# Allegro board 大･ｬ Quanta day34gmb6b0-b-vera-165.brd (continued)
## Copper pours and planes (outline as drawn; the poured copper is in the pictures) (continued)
GND on IN1 (solid shape): 76.93,83.49 76.93,80.16 76.73,79.96 75.39,79.96 74.93,79.5 74.37,79.5 74.32,79.45 74.28,79.43 74.25,79.45 73.2,80.49 73.2,82.8 74.15,83.75 74.63,83.75 75.15,84.26 76.16,84.26
GND on IN1 (solid shape): outline of 144 points within 94.31,44.17 101.62,55.45
GND on IN1 (solid shape): outline of 1586 points within 6.96,5.96 205.29,192.29
GND on IN1 (solid shape): outline of 4035 points within 0.51,0.51 149.88,159.9
GND on IN2 (solid shape): 24.23,118.34 24.23,115.72 24.18,115.67 21.61,115.67 21.54,115.75 21.54,118.31 21.59,118.36 24.2,118.36
GND on IN2 (solid shape): 154,117.83 154,114.73 153.82,114.55 150.95,114.55 150.7,114.81 150.7,117.98 150.95,118.24 153.59,118.24
GND on IN2 (solid shape): 175.92,74.09 175.92,72.7 175.79,72.57 175.16,72.57 175.03,72.7 175.03,74.09 175.16,74.22 175.79,74.22
GND on IN2 (solid shape): 187.09,16.05 187.09,10.59 186.94,10.44 182.85,10.44 182.5,10.8 182.5,15.75 183.18,16.43 186.71,16.43
GND on IN2 (solid shape): 24.13,75.01 24.13,73.43 24.08,73.38 22.45,73.38 22.4,73.43 22.4,75.01 22.45,75.06 24.08,75.06
GND on IN2 (solid shape): 63.73,19.56 63.73,16.87 63.73,16.87 61.03,16.87 61.03,16.87 61.03,19.56 61.03,19.56 63.73,19.56
GND on IN2 (solid shape): 26.54,108.92 26.54,105.51 26.24,105.21 22.78,105.21 22.55,105.44 22.55,105.51 22.38,105.69 22.38,108.64 22.88,109.14 26.31,109.14
GND on IN2 (solid shape): 76.93,83.49 76.93,80.16 76.73,79.96 75.41,79.96 74.73,79.27 74.5,79.27 73.2,80.57 73.2,82.96 74.55,84.3 76.12,84.3
GND on IN2 (solid shape): 165.12,183.57 165.12,139.12 154.96,128.96 154.96,126.42 154.46,125.91 142.77,125.91 140.74,127.94 132.36,127.94 131.6,128.7 128.55,128.7 126.52,130.73 119.4,130.73 117.12,133.02 107.72,133.02 103.15,137.59 103.15,157.4 103.66,157.91 158.52,157.91 158.77,158.17 158.77,158.93 158.27,159.44 103.4,159.44 103.15,159.69 103.15,169.6 109.24,175.69 116.1,175.69 125.5,185.09 147.34,185.09 148.87,186.61 162.08,186.61
GND on IN2 (solid shape): 193.34,76.46 193.34,71.59 193.4,71.53 193.4,71.01 193.58,70.84 193.58,70.75 193.56,70.74 193.41,70.42 193.58,70.12 193.58,66.16 193.19,65.78 193.19,63.81 192.56,63.17 192.56,62.19 191.49,61.12 191.12,61.12 191.08,61.08 191.05,61.08 190.79,60.98 190.67,60.74 190.66,60.69 184.72,60.69 184.19,61.22 184.19,74.83 185.23,75.87 187.65,75.87 187.73,75.83 187.75,75.74 188.1,75.23 188.48,75.71 188.47,75.74 189.08,76.35 189.19,76.37 189.26,76.28 189.74,75.94 189.98,76.48 189.98,76.58 190.07,76.63 193.18,76.63
GND on IN2 (solid shape): outline of 138 points within 93.93,44.02 101.47,57.73
GND on IN2 (solid shape): outline of 3473 points within 0.51,0.51 149.88,159.9
GND on SVCC (solid shape): 190.78,75.41 190.78,71.56 190.82,71.36 190.93,71.19 191.56,70.56 191.73,70.45 191.93,70.41 193.41,70.41 193.79,70.05 194.17,70.41 194.25,70.41 194.31,70.41 194.38,70.43 196.05,68.76 196.05,66.59 194.66,65.2 194.52,65.2 194.35,65.38 194.1,65.46 193.67,65.86 193.24,65.46 189.97,65.46 186.95,68.48 186.78,68.59 186.58,68.63 183.75,68.63 183.67,68.71 183.67,74.26 185.15,75.74 190.44,75.74
GND on SVCC (solid shape): 186.33,16.78 186.21,16.59 186.28,16.38 187.09,15.57 187.09,10.82 186.86,10.59 181.89,10.59 181.85,10.59 181.82,10.58 181.52,10.88 181.48,10.91 181.43,10.92 180.44,10.92 180.39,10.91 180.35,10.88 180.05,10.58 179.83,10.54 179.73,10.34 179.73,10.19 179.5,9.96 179.1,9.96 179,9.94 178.91,9.88 178.53,9.5 178.48,9.42 178.46,9.32 178.46,9.15 178,8.69 174.15,8.69 174.05,8.67 173.96,8.61 173.07,7.72 173.02,7.64 173,7.54 173,6.89 172.77,6.66 171.96,6.66 171.47,7.14 171.47,8.23 173.87,10.62 175.51,10.62 175.61,10.64 175.69,10.69 176.71,11.71 177.79,11.71 177.89,11.73 177.98,11.78 178.61,12.42 179.37,12.42 179.47,12.44 179.55,12.5 180.54,13.49 180.6,13.57 180.62,13.67 180.62,14.25 183.31,16.94 184.73,16.94 184.83,16.96 184.91,17.02 185.57,17.68 185.63,17.76 185.65,17.86 185.65,18.08 186.03,18.47 185.65,18.85 185.65,19.66 185.85,19.86 186.33,19.86
GND on SVCC (solid shape): outline of 357 points within 98.83,149.53 180.11,190.77
GND on SVCC (solid shape): outline of 100 points within 188.62,7.02 204.78,39.17
GND on SVCC (solid shape): outline of 4390 points within 1.02,1.02 202.33,190.8
PVCC2 on TOP (solid shape): 192.81,49.85 192.81,49.07 193.14,48.74 193.9,48.74 194,48.64 194,45.57 193.19,44.76 193.19,43.1 192.94,42.85 192.05,42.85 191.94,42.97 192.59,42.97 192.59,44.52 192.19,44.52 192.19,42.97 191.94,42.97 191.94,42.98 191.94,46.34 191.72,46.56 191.72,48.13 191.92,48.34 191.92,49.76 192.12,49.96 192.7,49.96
PVCC2 on TOP (solid shape): 184.05,48.69 184.05,47.68 184.04,47.63 184.02,47.61 184,47.59 183.98,47.58 183.95,47.57 183.89,47.59 183.83,47.6 183.78,47.6 183.72,47.6 183.67,47.58 183.61,47.56 183.57,47.53 183.52,47.5 183.48,47.45 183.45,47.41 183.43,47.36 183.41,47.3 183.4,47.25 183.4,47.19 183.41,47.14 183.43,47.08 183.45,47.03 183.48,46.98 183.52,46.94 183.57,46.91 183.61,46.88 183.67,46.86 183.72,46.84 183.78,46.84 183.83,46.84 183.89,46.85 183.95,46.86 183.98,46.86 184,46.85 184.02,46.83 184.04,46.8 184.05,46.76 184.05,45.14 184.55,44.63 184.93,44.63 184.96,44.6 184.96,44.6 185.04,44.5 185.04,42.96 184.94,42.85 184.17,42.09 184.17,39.25 184.01,39.09 184.01,37.35 183.5,36.84 183.46,36.84 183.4,36.82 183.35,36.8 183.3,36.77 183.28,36.75 182.27,36.75 182.14,36.88 182.14,42.97 184.79,42.97 184.79,44.52 184.39,44.52 184.39,42.97 182.14,42.97 182.14,48.69 182.27,48.82 183.92,48.82
PVCC2 on BOTTOM (solid shape): 185.34,47.8 192.2,47.8 192.3,47.7 192.3,46.81 192.15,46.66 184.94,46.66 184,47.59 183.87,47.59 183.77,47.6 183.67,47.58 183.66,47.58 183.63,47.58 183.41,47.8 183.41,48.69 183.54,48.82 184.33,48.82
1P35V_LGATE on TOP (solid shape): 99.95,53.47 99.95,51.64 100.25,51.33 100.25,40.66 99.97,40.37 99.02,40.37 98.89,40.5 98.89,41.99 98.91,42.05 98.92,42.1 98.92,42.8 98.92,42.82 99.02,42.96 99.05,43.1 99.05,43.94 98.9,44.09 98.88,44.1 98.88,44.12 98.88,50.11 98.42,50.57 98.42,53.57 98.63,53.77 99.64,53.77
1P35V_LGATE on BOTTOM (solid shape): 100.05,53.49 100.05,52.43 99.9,52.27 98.83,52.27 98.72,52.39 98.72,53.53 98.83,53.65 99.9,53.65
1P35V_PHASE on BOTTOM (solid shape): 100.75,51.25 100.75,50.42 100.69,50.37 99.49,50.37 99.13,50 99.13,49.06 98.89,48.82 98.5,48.82 96.44,46.76 96.44,44.32 95.31,43.19 92.7,43.19 92.58,43.31 92.58,47.93 93.65,49 93.65,49.98 95.37,49.98 95.98,50.6 95.98,51.33 96.31,51.66 100.34,51.66
1237LX on BOTTOM (solid shape): 190.27,73.84 190.27,73.17 190.74,72.7 191.38,72.7 191.52,72.56 191.52,71.01 192.3,70.24 192.3,69.54 192.3,69.54 192.3,69.39 192.35,69.34 193.04,69.34 193.06,69.32 193.06,65.99 192.97,65.9 192.06,65.9 192.05,65.91 192.05,66.25 192.1,66.29 192.1,68.48 192,68.58 190.8,68.58 189.7,67.48 188.89,67.48 188.73,67.64 188.73,68.52 188.43,68.82 191.82,68.82 191.82,69.07 191.37,69.07 191.37,68.82 188.43,68.82 187.53,69.72 187.53,73.63 187.8,73.9 190.21,73.9
8008LX1.5V on TOP (solid shape): 186.59,66.48 186.59,64.57 186.46,64.44 184.43,64.44 183.67,65.2 183.67,66.98 183.92,67.23 185.84,67.23
81101_BST on TOP (solid shape): 97.56,88.44 97.56,87.17 95.94,85.55 95.65,85.55 95.58,85.55 94.74,85.55 94.72,85.57 94.72,86.52 94.75,86.57 94.8,86.56 95.53,86.56 96.54,87.58 96.54,88.44 96.67,88.57 97.43,88.57
81101_HG on TOP (solid shape): 96.29,88.57 96.29,87.53 95.48,86.72 94.46,86.72 94.38,86.79 94.38,87.05 95.27,87.94 95.27,88.57 95.4,88.7 96.16,88.7
81101_HG_G on TOP (solid shape): 105.43,93.52 105.43,92.38 105.31,92.25 103.66,92.25 103.53,92.38 103.53,93.02 103.97,93.46 104.56,93.46 104.75,93.65 105.31,93.65
81101_HG_G on BOTTOM (solid shape): 109.74,93.9 109.74,92.44 109.58,92.28 108.34,92.28 108.34,93.15 109.27,94.08 109.55,94.08
81101_LG on TOP (solid shape): 93.75,90.98 93.75,88.82 93.37,88.44 93.37,87.05 93.24,86.92 92.86,86.92 92.73,87.05 92.73,90.98 92.86,91.11 93.62,91.11
81101_LG on TOP (solid shape): 104.93,95.43 104.93,94.16 104.8,94.03 104.77,94.03 104.37,93.62 103.48,93.62 103.33,93.78 103.33,94.51 103.53,94.72 103.53,95.43 103.66,95.56 104.8,95.56
81101_LG on BOTTOM (solid shape): 103.91,100.76 104.93,99.75 104.93,98.6 104.91,98.59 103.8,98.59 102.64,99.75 102.26,99.75 102.13,99.87 102.13,100.64 102.26,100.76 103.8,100.76
81101_LG on IN1 (solid shape): 104.91,100.01 104.91,99.23 104.93,99.21 104.93,93.98 104.44,93.49 103.37,93.49 103.16,93.7 103.16,93.94 103.18,93.96 103.29,94.1 103.33,94.28 103.33,94.29 103.53,94.49 103.53,95.76 103.55,95.78 103.56,95.79 103.83,96.19 103.56,96.59 103.55,96.6 103.53,96.62 103.53,97.07 103.53,97.09 103.55,97.11 103.73,97.46 103.55,97.81 103.53,97.83 103.53,97.85 103.53,99.62 103.4,99.75 102.13,99.75 102,99.87 102,100.64 102.13,100.76 104.16,100.76
81101_PH on TOP (solid shape): 110.39,101.52 110.39,94.7 110.35,94.65 110.32,94.61 110.3,94.56 110.28,94.51 110.27,94.46 110.27,94.4 110.27,94.35 110.28,94.3 110.3,94.25 110.32,94.2 110.35,94.16 110.39,94.1 110.39,92.38 110.26,92.25 105.85,92.25 105.85,93.73 108.99,93.73 108.99,93.67 109,93.61 109.01,93.56 109.04,93.5 109.07,93.45 109.11,93.41 109.15,93.37 109.2,93.33 109.25,93.3 109.3,93.28 109.36,93.27 109.42,93.27 109.48,93.27 109.54,93.28 109.59,93.3 109.65,93.33 109.69,93.37 109.74,93.41 109.78,93.45 109.81,93.5 109.83,93.56 109.85,93.61 109.85,93.67 109.85,93.73 109.85,93.79 109.83,93.85 109.81,93.9 109.78,93.95 109.74,94 109.69,94.04 109.65,94.07 109.59,94.1 109.54,94.12 109.48,94.13 109.42,94.13 109.36,94.13 109.3,94.12 109.25,94.1 109.2,94.07 109.15,94.04 109.11,94 109.07,93.95 109.04,93.9 109.01,93.85 109,93.79 108.99,93.73 105.85,93.73 105.85,101.63 105.99,101.78 110.13,101.78
81101_PH on BOTTOM (solid shape): 110.01,107.75 110.01,106.21 109.99,106.17 109.95,106.16 109.48,106.16 109.48,105.52 109.95,105.52 109.99,105.51 110.01,105.47 110.01,102.41 110.39,102.03 110.39,94.77 109.9,94.29 109.19,94.29 108.31,93.41 107.94,93.41 107.84,93.3 107.84,92.3 104.54,92.3 104.54,94.16 105.81,95.43 105.81,107.18 106.64,108 109.75,108
81181_AGND on BOTTOM (solid shape): 95.51,85.79 95.51,81.89 95.18,81.56 92.73,81.56 92.38,81.2 91.84,81.2 91.72,81.33 91.72,85.41 92.34,86.03 95.27,86.03
81181_AGND on IN2 (solid shape): 90.07,84.38 92.1,84.38 92.23,84.51 92.23,85.27 92.33,85.37 94.97,85.37 95.02,85.32 95.02,82.72 94.93,82.63 92.46,82.63 91.63,83.46 89.21,83.46 87.91,84.77 87.91,85.52 88.16,85.78 88.67,85.78
+AUDIO_5V_VDD on TOP (solid shape): 157.14,10.86 157.98,10.86 157.98,10.58 156.93,10.58 156.64,10.87 155.85,10.87 155.85,11.28 156.72,11.28
+AUDIO_5V_VDD on TOP (solid shape): outline of 363 points within 144.42,5.49 152.32,9.96
+BATCHG on BOTTOM (solid shape): outline of 403 points within 100.19,176.91 121.49,186.33
+PRWSRC on TOP (solid shape): 84.82,176.41 84.82,175.95 83.57,174.7 81.68,174.7 81.58,174.8 81.58,175.26 81.68,175.36 82.8,175.36 84.01,176.57 84.66,176.57
+PRWSRC on BOTTOM (solid shape): outline of 380 points within 83.59,174.9 101.47,185.75
+SMDDR_VREF_DQ1 on TOP (solid shape): 109.37,41.44 109.37,40.06 109.24,39.93 108.61,39.93 108.48,39.8 108.48,37.9 108.61,37.77 108.99,37.77 109.37,37.39 109.37,34.72 109.12,34.47 107.47,34.47 107.08,34.85 107.08,41.52 107.28,41.71 109.11,41.71
+SMDDR_VREF_DQ1 on BOTTOM (solid shape): 112.53,48.58 112.53,46.64 112.29,46.41 111.69,46.41 111.67,46.41 111.65,46.42 111.36,46.53 111.1,46.37 110.84,46.11 110.1,46.11 109.83,46.38 108.97,46.73 108.41,46 108.41,34.65 108.1,34.34 106.83,34.34 106.32,34.85 106.32,46.41 108.61,48.69 112.42,48.69
+VA on BOTTOM (solid shape): 73.41,184.48 73.41,179.02 73.26,178.87 73.18,178.93 72.65,179.44 72.88,178.74 72.98,178.68 72.96,178.57 72.49,178.11 71.32,178.11 71.17,178.26 71.17,178.64 71.2,178.72 71.29,178.74 71.65,178.88 71.7,179.27 71.34,179.5 70.99,179.26 70.98,179.22 68.83,179.22 68.71,179.35 68.71,180.59 68.82,180.71 69.3,180.71 69.38,180.71 69.57,180.9 69.57,184.35 69.82,184.61 73.29,184.61
+VA_AC on TOP (solid shape): 36.32,184.4 37.08,183.92 37.95,183.69 38.38,183.26 38.38,181.35 36.33,179.3 34.25,179.3 34.06,179.49 34.06,183.9 34.57,184.4
+VA_AC on BOTTOM (solid shape): 68.88,184.68 68.88,181.31 68.47,180.9 66.95,180.9 65.16,182.7 65.15,182.71 65.06,182.85 64.92,182.93 64.91,182.94 64.67,183.19 42.82,183.19 42.06,182.42 41.06,182.42 41.05,182.42 38.5,182.42 37.62,181.53 37.62,178.9 35.86,177.15 34.55,177.15 34.45,177.25 34.45,178.57 34.06,178.96 34.06,184.36 34.59,184.89 67.87,184.89 68.09,184.9 68.65,184.9
+VA_AC on IN1 (solid shape): 67.73,184.42 67.73,183.05 67.73,183.05 67.73,182.03 67.46,181.76 66.14,181.76 65.69,182.21 65.21,182.69 65.16,182.74 65.06,182.85 65.01,182.89 64.18,183.72 38.67,183.72 37.6,182.65 37.6,179.86 37.01,179.28 34.54,179.28 34.11,179.7 34.11,184.09 34.6,184.58 67.57,184.58
+VA_AC on IN2 (solid shape): outline of 204 points within 33.81,181.28 68.1,184.41
+VAD on BOTTOM (solid shape): 82.5,182.09 82.5,176 82.09,175.6 80.4,175.6 79.16,174.36 79.16,173.2 78.95,173 76.71,173 76.3,173.41 76.3,179.86 75.79,180.37 74.04,180.37 73.96,180.44 73.96,182.14 74.17,182.35 82.24,182.35
BATDIS_G on BOTTOM (solid shape): 88.22,182.44 89.19,181.47 89.2,181.46 89.22,181.46 89.6,181.46 89.61,181.45 89.74,181.45 89.89,181.31 89.89,179.55 89.68,179.34 89.66,179.33 89.64,179.32 89.11,179.32 89.09,179.33 88.65,179.33 87.29,180.7 85.44,180.7 85.41,180.71 85.39,180.75 85.39,182.25 85.56,182.42 85.57,182.44 85.59,182.44 87.4,182.44 87.45,182.45 88.2,182.45
BATT+ on TOP (solid shape): 143.66,191.06 143.66,189.46 146,187.12 148.84,187.12 149.2,186.76 149.2,179.27 148.78,178.84 139.75,178.84 139.47,179.12 139.47,182.88 148.69,182.88 148.69,184.23 148.2,184.23 148.2,182.88 147.7,182.88 147.7,184.23 147.2,184.23 147.2,182.88 146.7,182.88 146.7,184.23 146.2,184.23 146.2,182.88 145.7,182.88 145.7,184.23 145.2,184.23 145.2,182.88 144.7,182.88 144.7,184.23 144.2,184.23 144.2,182.88 143.7,182.88 143.7,184.23 143.2,184.23 143.2,182.88 142.7,182.88 142.7,184.23 142.2,184.23 142.2,182.88 139.47,182.88 139.47,183.67 139.48,183.68 139.48,183.96 140.99,185.47 140.99,187.2 139.98,188.21 139.98,190.81 140.49,191.31 143.41,191.31
BATT+ on BOTTOM (solid shape): outline of 501 points within 120.64,180.81 143.64,191.54
BQB_1 on TOP (solid shape): 97.94,181.25 97.94,179.42 97.77,179.25 95.38,179.25 95.3,179.32 95.3,181.25 95.43,181.38 97.81,181.38
BQB_2 on TOP (solid shape): 93.78,179.91 94.21,179.91 94.28,179.98 94.28,180.01 95.1,180.01 95.15,179.96 95.15,179.25 95.05,179.15 93.95,179.15 93.11,179.98 92.3,179.98 92.25,180.04 92.25,180.21 92.3,180.26 93.42,180.26
BQHIDRV on TOP (solid shape): 94.26,180.82 94.26,180.42 94.11,180.26 93.75,180.26 93.55,180.47 92.3,180.47 92.25,180.52 92.25,180.75 92.28,180.77 93.62,180.77 93.78,180.92 94.16,180.92
BQHIDRV on TOP (solid shape): 104.21,181.36 104.21,180.44 104.2,180.43 103.34,180.43 103.3,180.47 103.3,181.41 103.43,181.53 104.04,181.53
BQLODRV on TOP (solid shape): 93.11,179.17 93.11,178.66 92.94,178.49 91.9,178.49 91.82,178.56 91.82,179.3 92.99,179.3
BQLODRV on TOP (solid shape): 105.74,181.86 105.74,181.18 105.26,180.7 104.65,180.7 104.47,180.87 104.47,181.15 105.23,181.92 105.69,181.92
BQLR on BOTTOM (solid shape): 113.12,178.41 113.12,177.53 114.37,176.28 114.46,176.28 114.46,176.26 115.1,176.26 115.1,176.28 115.7,176.28 115.71,176.29 115.87,176.12 115.87,175.23 115.86,175.22 115.86,174.67 115.86,174.67 115.86,174.5 115.58,174.22 112.11,174.22 111.3,175.03 111.3,178.57 111.43,178.7 112.83,178.7
BQPHASE on TOP (solid shape): 95.07,181.36 95.07,180.9 94.99,180.82 94.61,180.82 94.36,181.08 93.57,181.08 93.47,180.98 92.28,180.98 92.25,181 92.25,181.25 92.28,181.28 93.24,181.28 93.39,181.43 94.99,181.43
BQPHASE on TOP (solid shape): 108.02,180.11 108.02,178.69 108.41,178.31 109.19,178.31 109.57,177.93 109.57,177.17 107.62,175.21 104.24,175.21 103.91,175.54 103.91,176.48 103.96,176.53 103.96,177.5 103.43,178.03 103.43,180.09 103.55,180.21 104.87,180.21 105.13,180.47 107.67,180.47
BQPHASE on BOTTOM (solid shape): 108.03,178.14 108.03,175.13 107.35,174.45 104.85,174.45 103.78,175.51 103.78,176.56 104.07,176.84 104.07,177.29 105.35,178.58 107.59,178.58
L_SPK+ on TOP (solid shape): 85.72,168.88 85.72,168.45 85.65,168.38 83.11,168.38 83.01,168.48 83.01,168.91 83.11,169.01 85.6,169.01
L_SPK+ on TOP (solid shape): 185.92,18.58 185.92,17.67 185.82,17.58 185.82,16.43 185.75,16.36 185.65,16.36 185.57,16.43 185.57,17.58 185.42,17.73 185.42,18.61 185.53,18.72 185.78,18.72
L_SPK+ on IN1 (solid shape): 91.94,10.07 91.94,9.15 91.79,9 91.29,9 90.7,9.59 90.7,9.6 90.55,9.75 90.55,10.06 90.7,10.22 91.8,10.22
L_SPK+ on IN1 (solid shape): 186.31,18.62 186.31,16.74 186.03,16.46 185.67,16.46 185.52,16.61 185.52,17.6 185.52,18.72 185.62,18.82 186.1,18.82
L_SPK+ on IN2 (solid shape): 91.87,11.8 91.87,9.85 91.72,9.7 90.71,9.7 90.56,9.85 90.56,11.65 90.8,11.9 91.78,11.9
L_SPK- on TOP (solid shape): 85.72,170.31 85.72,169.88 85.65,169.8 83.11,169.8 83.01,169.9 83.01,170.33 83.11,170.43 85.6,170.43
L_SPK- on TOP (solid shape): 185.27,18.63 185.27,17.74 185.32,17.7 185.32,16.43 185.24,16.36 185.14,16.36 185.06,16.43 185.06,17.45 184.81,17.7 184.77,17.74 184.77,18.61 184.88,18.72 185.19,18.72
L_SPK- on IN1 (solid shape): 94.17,10.07 94.17,9.7 94.04,9.57 92.46,9.57 92.2,9.83 92.2,10.13 92.29,10.22 94.03,10.22
L_SPK- on IN1 (solid shape): 185.27,18.67 185.27,16.92 184.91,16.56 184.53,16.56 184.1,16.13 183.67,16.13 183.41,16.38 183.41,16.51 184.25,17.35 184.61,17.35 184.83,17.58 184.83,18.64 184.91,18.72 185.22,18.72
L_SPK- on IN2 (solid shape): 93.34,9.83 93.22,9.7 92.33,9.7 92.2,9.83 92.2,11.41 92.48,11.69 93.34,11.69
PD#_R on TOP (solid shape): 161.61,14.15 161.61,13.63 161.52,13.54 160.3,13.54 160.18,13.42 160.18,12.28 159.9,12.28 159.9,13.11 159.68,13.11 159.68,12.28 159.4,12.28 159.4,14.21 159.47,14.29 161.47,14.29
R_SPK+ on TOP (solid shape): 85.72,173.1 85.72,172.67 85.65,172.59 83.11,172.59 83.01,172.69 83.01,173.13 83.11,173.23 85.6,173.23
R_SPK+ on TOP (solid shape): 183.92,18.59 183.92,17.7 183.79,17.58 183.79,16.43 183.72,16.36 183.61,16.36 183.54,16.43 183.54,17.58 183.46,17.65 183.46,18.64 183.54,18.72 183.79,18.72
R_SPK+ on IN1 (solid shape): 115.95,10.31 115.95,9.8 115.82,9.68 113.54,9.68 113.41,9.8 113.41,10.31 113.54,10.44 114.4,10.44 115.82,10.44
R_SPK+ on IN1 (solid shape): 183.87,18.67 183.87,17.25 183.23,16.61 182.98,16.61 182.88,16.71 182.88,17.32 183.11,17.55 183.11,18.54 183.28,18.72 183.82,18.72
R_SPK+ on IN2 (solid shape): 114.55,10.67 114.55,9.91 114.43,9.78 113.54,9.78 113.41,9.91 113.41,10.54 113.16,10.8 112.01,10.8 111.89,10.92 111.89,11.43 112.01,11.56 113.66,11.56
R_SPK- on TOP (solid shape): 85.72,171.7 85.72,171.27 85.65,171.2 83.11,171.2 83.01,171.3 83.01,171.73 83.11,171.83 85.6,171.83
R_SPK- on TOP (solid shape): 184.55,18.59 184.55,17.7 184.3,17.45 184.3,16.43 184.22,16.36 184.12,16.36 184.05,16.43 184.05,17.7 184.05,17.71 184.07,17.83 184.05,17.96 184.05,17.96 184.05,18.33 184.05,18.34 184.07,18.45 184.06,18.57 184.05,18.58 184.06,18.61 184.17,18.72 184.43,18.72
R_SPK- on IN1 (solid shape): 114.4,11.28 114.4,10.77 114.32,10.69 113.43,10.69 113.38,10.64 113.13,10.64 113,10.52 113,10.01 112.88,9.88 111.99,9.88 111.86,10.01 111.86,11.02 112.24,11.4 114.27,11.4
R_SPK- on IN1 (solid shape): 184.58,18.96 184.58,17.68 184.48,17.58 184.17,17.58 184.12,17.63 184.12,18.62 183.87,18.88 183.35,18.88 183.28,18.94 183.28,19.36 183.37,19.45 184.09,19.45
R_SPK- on IN2 (solid shape): 113.03,10.41 113.03,9.91 112.9,9.78 111,9.78 110.87,9.91 110.87,10.41 111,10.54 112.9,10.54
RF_LINK# on BOTTOM (solid shape): 195.65,158.53 195.65,156.08 194.34,156.08 194.34,158.55 194.49,158.7 195.48,158.7
SM_VREF on TOP (solid shape): 138.28,85.06 138.28,84.23 138.25,84.2 138.21,84.19 138.2,84.2 137.81,84.18 137.64,83.83 137.61,83.75 137.54,83.72 137.11,83.72 136.9,83.92 136.9,84.74 137.28,85.12 137.33,85.18 137.38,85.24 137.4,85.26 137.42,85.27 138.07,85.27
SUB_OUT on TOP (solid shape): 188.42,17.91 188.42,17.68 188.26,17.53 188.11,17.53 188.11,17.53 187.81,17.53 187.48,17.2 187.48,16.56 187.28,16.36 187.09,16.36 187.04,16.42 187.04,17.41 187.04,17.42 187.04,17.65 187.42,18.03 188.29,18.03
SUB_OUT on BOTTOM (solid shape): 188.69,20.73 188.69,17.96 188.31,17.58 188.11,17.58 187.88,17.35 187.88,16.97 188.26,16.59 188.26,16.23 188.21,16.18 187.42,16.18 187.02,16.58 187.02,17.67 187.63,18.28 187.63,18.47 187.71,18.55 187.71,19.6 187.19,20.12 186.59,20.12 186.59,20.7 186.82,20.93 188.49,20.93
SUB_OUT+ on TOP (solid shape): 191.11,132.66 191.14,132.65 191.16,132.61 191.16,129.71 192.07,128.79 192.07,128.47 191.82,128.22 189.81,128.22 189.76,128.27 189.76,130.35 190.02,130.61 190.02,131.39 190.4,131.77 190.4,132.38 190.69,132.66
SUB_OUT+_L_4P on TOP (solid shape): 129.16,8.91 129.16,8.75 129.01,8.6 128.06,8.6 127.95,8.71 127.95,9.66 128.05,9.76 128.31,9.76
SUB_OUT+_L_4P on TOP (solid shape): 163.24,10.47 163.24,10.21 163.12,10.08 161.09,10.08 161.09,10.36 162.02,10.36 162.26,10.59 163.12,10.59
SUB_OUT+_L_4P on BOTTOM (solid shape): 129.23,8.92 129.23,8.33 129.11,8.2 128.09,8.2 127.91,8.38 127.91,8.97 128.07,9.13 129.03,9.13
SUB_OUT+_L_4P on BOTTOM (solid shape): 163.29,10.47 163.29,9.96 163.12,9.78 161.87,9.78 161.54,10.11 161.54,10.57 161.69,10.72 163.04,10.72
SUB_OUT+_R_4P_1 on TOP (solid shape): 157,10.36 157.98,10.36 157.98,10.08 156.69,10.08 156.65,10.12 156.33,10.12 156.3,10.08 155.86,10.08 155.73,10.21 155.73,10.47 155.85,10.59 156.76,10.59
SUB_OUT+_R_4P_15 on TOP (solid shape): 193.46,132.36 193.46,129.95 194.26,129.16 197.99,129.16 198.14,129.31 198.58,129.31 198.69,129.2 198.69,128.08 198.63,128.02 193.75,128.02 191.79,129.97 191.79,132.51 191.95,132.66 193.16,132.66
SUB_OUT+_R_4P_15 on IN2 (solid shape): 198.96,129.29 198.96,128.04 198.85,127.94 197.51,127.94 197.38,128.07 197.38,129.21 197.65,129.48 198.77,129.48
SUB_OUT+_R_C on TOP (solid shape): 81.6,6.15 81.6,5.57 81.51,5.49 78.71,5.49 78.71,6.21 78.73,6.25 78.76,6.26 81.49,6.26
SUB_OUT- on TOP (solid shape): 192.05,127.56 192.05,127.05 190.97,125.97 190.97,123.13 190.96,123.11 190.53,123.11 190.07,123.11 189.89,123.29 189.89,123.76 189.89,123.76 189.89,125.15 189.76,125.27 189.76,127.64 189.84,127.71 191.9,127.71
SUB_OUT-_L_4P on TOP (solid shape): 127.4,9.02 127.4,8.59 127.33,8.51 125.39,8.51 125.32,8.58 125.32,9.04 125.4,9.12 127.3,9.12
SUB_OUT-_L_4P on TOP (solid shape): 163.22,11.99 163.22,11.68 163.12,11.58 161.09,11.58 161.09,11.86 161.95,11.86 162.2,12.12 163.09,12.12
SUB_OUT-_L_4P on BOTTOM (solid shape): 163.45,12.32 163.45,11.58 163.35,11.48 162.25,11.48 162.05,11.68 162.05,12.62 162.1,12.67 163.09,12.67
SUB_OUT-_R_4P_1 on TOP (solid shape): 157.12,11.86 157.98,11.86 157.98,11.58 155.98,11.58 155.85,11.71 155.85,11.99 155.98,12.11 156.87,12.11
SUB_OUT-_R_4P_15 on TOP (solid shape): 198.6,127.36 198.6,126.54 198.42,126.37 198.17,126.37 198.13,126.41 198.09,126.45 198.04,126.49 198,126.49 197.86,126.52 197.73,126.49 194.28,126.49 193.34,125.55 193.34,123.09 193.19,122.94 191.74,122.94 191.6,123.08 191.6,125.21 193.9,127.51 198.45,127.51
SUB_OUT-_R_4P_15 on IN2 (solid shape): 199.43,127.4 199.43,125.72 199.24,125.53 198.14,125.53 198.02,125.65 198.02,127.36 198.22,127.56 199.28,127.56
SUB_OUT-_R_C on TOP (solid shape): 82.52,7.42 82.52,6.81 82.47,6.76 81.02,6.76 81.01,6.74 78.67,6.74 78.58,6.83 78.58,7.49 78.62,7.52 82.42,7.52
SUB_OUT_L+ on TOP (solid shape): 163.93,8.94 164.79,8.94 165.1,8.64 165.1,8.51 165.02,8.43 164.99,8.44 163.72,8.44 163.72,8.43 163.42,8.43 162.89,7.9 161.62,7.9 161.19,8.32 160.4,8.32 160.4,9.16 161,9.16 161.06,9.22 163.65,9.22
SUB_OUT_LC on TOP (solid shape): 160.4,6.57 160.4,4.93 160.35,4.88 159.89,4.88 159.76,5 159.76,6.57 159.85,6.66 160.31,6.66
SUB_OUT_LR on TOP (solid shape): 166.95,7.26 166.95,7.06 166.37,6.48 165.85,6.48 165.74,6.48 165.4,6.82 165.4,7.26 165.48,7.34 166.87,7.34
SUB_OUT_LR on TOP (solid shape): 160.18,8.31 160.29,8.19 161.14,7.35 161.14,6.96 160.96,6.78 159.92,6.78 159.87,6.83 159.87,7.26 159.92,7.4 159.9,7.56 159.9,7.56 159.9,9.16 160.18,9.16
SUB_OUT_R+ on TOP (solid shape): 158.68,8.32 157.14,8.32 156.85,8.04 156.3,8.04 155.98,7.72 155.67,7.72 155.24,7.29 154.96,7.29 154.96,7.29 153.69,7.29 153.67,7.32 153.67,7.62 154,7.95 155.12,7.95 155.34,8.18 155.34,8.81 155.69,9.16 158.68,9.16
SUB_OUT_RC on TOP (solid shape): 159.15,6.55 159.15,5.03 158.98,4.85 158.6,4.85 158.52,4.93 158.52,6.55 158.63,6.66 159.05,6.66
SUB_OUT_RR on TOP (solid shape): 159.18,6.99 159.05,6.86 158.65,6.86 158.39,6.6 158.39,5.99 157.99,5.59 156.09,5.59 155.92,5.76 155.92,6.19 156,6.27 157,6.27 157,6.27 157.22,6.27 157.47,6.52 157.47,6.67 157.79,6.99 157.98,7.11 158.09,7.3 158.9,8.1 158.9,9.16 159.18,9.16
SY8208BSW on BOTTOM (solid shape): 53.3,48.62 53.62,48.31 55.33,48.31 55.92,47.72 55.92,47.22 56.5,46.64 57.55,46.64 57.6,46.6 57.6,46.17 57.48,46.05 56.79,46.05 56.25,45.52 48.54,45.52 48.16,45.9 48.16,47.3 47.9,47.55 47.9,48.06 48.03,48.18 51.59,48.18 52.16,48.76 52.16,49.98 53.3,49.98
SY8208CSW on BOTTOM (solid shape): 34.22,52.68 34.24,52.67 34.26,52.66 34.57,52.5 34.88,52.66 34.89,52.67 34.92,52.68 35.71,52.68 35.79,52.6 35.79,51.31 36.07,51.03 37.18,51.03 38.24,49.98 38.25,49.97 39.18,49.97 39.81,50.6 41.43,50.6 41.47,50.58 41.48,50.55 41.48,49.38 41.47,49.34 41.43,49.33 40.23,49.33 40.16,49.33 39.21,48.38 33.91,48.38 33.62,48.68 33.62,51.02 33.83,51.23 33.83,52.43 34.09,52.68
VBOOT on TOP (solid shape): 91.97,86.41 92.1,86.41 92.23,86.54 92.48,86.54 92.52,86.49 92.52,85.57 92.51,85.54 92.47,85.52 91.59,85.52 91.59,85.52 91.48,85.52 91.27,85.73 91.27,86.14 90.93,86.49 90.93,86.77 91.08,86.92 91.46,86.92
N17271649 on BOTTOM (solid shape): 93.03,15.9 93.26,15.8 93.54,15.87 93.57,15.86 93.59,15.83 93.75,15.83 93.77,15.85 95.27,15.85 95.3,15.82 95.31,15.8 95.32,15.78 95.32,15.6 95.26,15.55 93.75,15.55 93.75,15.35 95.25,15.35 95.32,15.28 95.32,14.97 95.25,14.91 93.62,14.91 93.16,14.44 92.49,14.44 91.59,15.34 91.59,16.05 91.84,16.31 92.63,16.31
N17271663 on BOTTOM (solid shape): 93.56,33.86 93.56,33 93.72,32.83 95.28,32.83 95.34,32.78 95.34,32.6 95.32,32.56 95.29,32.55 93.75,32.55 93.75,32.35 95.29,32.35 95.32,32.34 95.34,32.3 95.34,32.1 95.32,32.06 95.29,32.05 92.41,32.05 91.73,32.74 91.73,33.97 91.94,34.18 93.24,34.18
N17595064 on TOP (solid shape): 19.12,35.99 19.12,30.53 15.22,26.63 15.22,21.09 17.23,19.08 17.23,9.74 21.16,5.82 22.1,5.82 22.68,5.23 25.2,5.23 25.29,5.14 25.29,0.51 11.04,0.51 10.09,0.7 9.28,1.24 5.66,4.86 5.66,5.11 5.81,5.26 8.91,5.26 9.14,5.49 11.82,5.49 12.19,5.86 12.19,8.63 9.93,10.89 9.93,29.2 16.55,35.82 16.55,37.06 16.71,37.21 17.9,37.21
N17595064 on BOTTOM (solid shape): 19.05,36.09 19.05,35.2 18.92,35.07 17.43,35.07 17.14,35.36 17.14,36.97 17.26,37.09 18.04,37.09
N17595064 on BOTTOM (solid shape): 25.29,5.05 25.29,0.51 11.04,0.51 10.04,0.72 9.21,1.33 9.17,1.39 7.13,3.4 7.13,4.42 7.97,5.26 12.09,5.26 14.12,7.29 23.05,7.29
N20722048 on BOTTOM (solid shape): 58.27,182.6 58.27,181.38 58.06,181.18 56.51,181.18 56.41,181.28 55.14,181.28 55.01,181.41 55.01,182.42 55.38,182.79 58.08,182.79
N21913817 on TOP (solid shape): 169.57,126.04 170.84,126.04 171.09,125.78 171.09,121.72 170.97,121.59 168.89,121.59 168.81,121.67 168.81,125.89 168.96,126.04 169.57,126.04
N23235545 on BOTTOM (solid shape): 22.44,171.88 22.44,171.6 22.41,171.53 22.35,171.5 21.99,171.12 22.35,170.74 22.41,170.71 22.44,170.64 22.44,168.07 22.19,167.82 20.24,167.82 18.39,169.67 18.3,169.75 18.21,169.81 18.19,169.83 18.18,169.85 18.18,171.76 18.57,172.14 22.19,172.14
N23235545 on IN2 (solid shape): outline of 833 points within 15.52,137.59 21.74,170.23
N26154223 on TOP (solid shape): 186.59,63.93 186.59,62.15 186.46,62.03 184.34,62.03 184.2,62.17 184.2,63.02 184,63.22 183.54,63.22 183.31,63.45 183.31,64.08 183.41,64.19 186.33,64.19
N26154319 on BOTTOM (solid shape): 188.5,68.22 188.5,66.41 188.43,66.33 187.4,66.33 187.29,66.44 187.29,68.26 187.44,68.41 188.31,68.41
N34547582 on TOP (solid shape): 94.61,45.69 94.61,44.93 94.77,44.78 94.77,44.17 94.61,44.02 93.85,44.02 93.7,44.17 93.7,45.69 93.85,45.85 94.46,45.85

Small or netless copper shapes (teardrops, artwork), in the pictures only: 69 on TOP, 41 on BOTTOM, 43 on IN1, 100 on IN2

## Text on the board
Ref Des/Silkscreen Bottom: REV:B | DAY34GMB6B0 | MODEL:Y34G
User.Comments: PARTITION_2 | 16.0x24.0 | 31.0x106.0 | 142.0x150.0 | OUTLINE
Ref Des/Silkscreen Top: DAY34GMB6B0 | REV:B
DISPLAY_BOTTOM: B
User.6: +VIN | AGND | GND | +5V_USBP0 | +5V_USBP1 | +VCC_CORE | +1.05V | +3VS5 | +5V
User.17: GND | AGND
User.22: BOTTOM
User.24: TOP         COMPONENT
User.25: HEIGHT
User.35: Y11A-MB | DATE | 03/28/14' | PROJECT | LAYER | REV. | SVCC | 5 | E | DAY11AMB6E0 | 16.5
User.38: B | A | Q40 | 5 | 4 | R598 | C770 | H20 | R597 | R596 | R592 | 8 | R599 | VC4 | C758 | C760 | R587 | C763 | R594 | C772 | C768 | PC45 | EC2 | PJP3 | PC5 | PL20 | PC189 | PC191 | PC193 | PC196 | Q7030 | PC211 | PR183 | PR184 | R7465 | PR185 | C7747 | PD10 | C7748 | Q7031 | PC192 | PC195 | C765 | PR173 | PR174 | C29 | PJP4 | C761 | PC204 | PR177 | PR179 | PC209 | PR143 | R23 | PR144 | PL4 | PL6 | EC1 | C759 | C750 | C756 | C757 | PQ20 | PD9 | PC231 | C766 | PL19 | PC194 | PC207 | 3 | PR163 | PR164 | PC56 | PR88 | PL22 | C749 | C748 | C762 | C641 | C644 | PC129 | PC174 | PC210 | PL15 | PC197 | PC208 | PC230 | PC217 | PC172 | PJP2 | PC215 | PC133 | PL9 | PC137 | PC142 | PL8 | C172 | C178 | C181 | T | R | R443 | P | C170 | N | PC166 | C719 | M | C179 | C182 | L | K | C168 | PC168 | J | C180 | H | G | C171 | PL7 | F | PL5 | C183 | PL14 | R580 | PC126 | E | R522 | R554 | R562 | R501 | R508 | R509 | R542 | R547 | R564 | D | C | C173 | 1 | 9 | 7 | 2 | R494 | R495 | R496 | R537 | R543 | R548 | VRAM4 | R506 | R517 | R521 | R531 | VRAM3 | C739 | C745 | C740 | C746 | TP20 | C705 | C711 | TP40 | C698 | C701 | R111 | C689 | C693 | Y5 | C707 | C688 | C690 | R141 | R440 | R441 | R445 | R447 | R450 | R118 | R121 | R130 | R133 | R137 | R437 | R438 | R442 | R446 | R589 | R120 | R122 | R132 | R134 | R135 | R138 | R534 | R538 | R545 | R553 | C297 | R585 | R574 | C710 | R590 | R546 | R552 | R519 | R524 | R535 | R139 | U22 | R483 | R487 | R500 | R504 | R591 | R511 | R520 | R525 | R536 | R544 | CN22 | C716 | R505 | C169 | C741 | C724 | R631 | C175 | R588 | R510 | R518 | R523 | R567 | R565 | PL13 | PL11 | R7471 | R488 | R489 | R490 | R492 | R493 | R570 | R572 | C647 | C651 | 16 | PC175 | PC161 | PC162 | 15 | C653 | R568 | R569 | EC72 | PJP1 | 17 | 18 | C726 | R609 | R618 | Q38 | EC81 | U24 | R7470 | R608 | R549 | C803 | PC177 | C804 | PC184 | EC76 | PC185 | C805 | R616 | C715 | C731 | C712 | C733 | C725 | EC75 | C734 | C732 | R458 | PR155 | PC152 | PC156 | R617 | PC146 | PC149 | PC150 | PC151 | 52 | 51 | R611 | R612 | C806 | EC82 | L47 | R613 | U* | 12 | 11 | 10 | R439 | C764 | CN20 | C747 | PC190 | H7 | PU12 | PC219 | 6 | PR187 | R7467 | PC218 | PR180 | PU11 | U2 | L8 | PR188 | C48 | PC198 | H22 | PQ33 | PR208 | PD7 | CN26 | PC148 | 58 | 68 | PU9 | 74 | L36 | L39 | PR72 | PQ39 | PQ31 | C174 | C176 | C177 | 23 | 75 | 67 | 57 | PQ29 | PR146 | PR139 | PR138 | PR136 | PR161 | TP26 | TP34 | TP36 | BAT14 | AK | Y | AB | AF | AP | AY | TP37 | AH | AM | AV | AT | V | AD | TP18 | 63 | 62 | 61 | 60 | 59 | 27 | 71 | 56 | 72 | 26 | 55 | 25 | 54 | PC141 | 53 | 24 | 73 | C738 | C744 | 22 | 50 | 21 | 49 | 48 | 20 | 47 | 19 | 46 | BAT15 | FAN1 | 45 | 44 | 43 | 42 | 41 | 40 | 14 | 13 | 39 | C736 | C742 | 38 | U25 | 37 | 36 | JDIM2 | 35 | C743 | C737 | JDIM1 | 34 | 33 | 32 | 31 | 30 | Q32 | 29 | 28 | U | AC | AG | U29 | AE | AA | L46 | Q9 | W | R632 | PC154 | AN | AU | AW | AR | AL | AJ | RP6 | PC147 | PC153 | TP35 | RP5 | 203 | 204 | R610 | C652 | TP33 | C735 | PQ22 | TP29 | U23 | PR168 | PQ26 | PQ27 | PR170 | PQ23 | PQ28 | PQ21 | PQ25 | PC167 | R615 | PU10 | PR166 | C8739 | C767 | VC5 | C769 | U27 | C608 | R600 | R595 | C774 | C771 | PC220 | PC46 | PC221 | PC200 | PC222 | PC199 | PC224 | C751 | PC223 | C752 | R7466 | C753 | PL17 | C754 | PR182 | PC214 | C21 | PC206 | PC187 | PC202 | PL21 | PL18 | PC203 | PC228 | C37 | C755 | PC226 | PC188 | EC77 | PC227 | R31 | R7468 | PC225 | PC213 | PC229 | C19 | PR206 | PR209 | PR207 | PR210 | PC212 | R603 | PC118 | PL10 | EC42 | EC64 | EC66 | PR22 | PR147 | PC136 | PR93 | PR148 | C778 | PR149 | PC61 | PC173 | C779 | C780 | PC171 | PR150 | PC48 | C782 | PC49 | PR151 | PC143 | PC244 | PR211 | EC9 | EC7 | PR160 | EC6 | EC8 | PR9 | PR162 | R555 | R556 | PC164 | PR137 | R557 | PC130 | C718 | PC128 | PC165 | R533 | PC124 | PC122 | PC120 | PC121 | C162 | C163 | R107 | PC127 | R108 | TP31 | C164 | C165 | PC123 | R455 | R482 | C702 | C703 | C704 | C686 | R112 | R115 | C184 | C687 | R113 | R116 | R451 | C691 | R114 | R117 | C692 | R109 | C185 | R110 | R453 | R452 | R456 | TP41 | C166 | TP39 | C167 | TP38 | R457 | TP19 | R583 | R584 | C708 | R484 | R448 | R581 | R485 | R449 | R499 | R502 | R126 | R575 | R129 | R576 | R550 | PL12 | R577 | R551 | R578 | R512 | R526 | R539 | R579 | R486 | R513 | R527 | R540 | R507 | R514 | R528 | R541 | R593 | R497 | R515 | R529 | R558 | R498 | R516 | R7473 | PR157 | R559 | R560 | J1 | R566 | R491 | C713 | C714 | TP25 | R7472 | PL23 | R561 | R563 | R571 | PL16 | PC179 | PC145 | PC178 | C720 | R530 | Q39 | R532 | C717 | C797 | PC180 | PC176 | C798 | R622 | C729 | C727 | PC181 | R623 | PC182 | C799 | C723 | PR171 | C800 | C730 | Q41 | C722 | C728 | PR172 | EC80 | EC79 | PC157 | PC163 | C649 | PC155 | PC160 | PC183 | PC158 | EC78 | CN24 | R454 | CN28 | CN21 | CN25 | C776 | PR175 | PR176 | PR181 | PC205 | PC216 | PR178 | PQ38 | PC119 | R342 | PQ32 | CN29 | EC45 | PR145 | PR153 | PR186 | PD8 | PR221 | PR222 | PR152 | PC201 | PR189 | PQ30 | PR158 | TP27 | PR159 | C158 | C159 | C160 | C161 | C186 | C187 | C188 | C189 | C190 | C706 | C191 | C192 | C193 | C194 | C195 | C696 | C697 | C694 | C699 | C695 | C700 | PC125 | L44 | L45 | C83 | R123 | R503 | C84 | PC159 | TP21 | TP22 | R586 | C650 | TP32 | CN27 | U26 | PQ24 | C801 | PC186 | C802 | PR165 | PR154 | C721 | R614 | ODD14 | U28 | PR156 | PR167 | PR169 | D13 | Y11A-MB | DATE | 03/28/14' | PROJECT | LAYER | REV. | SK_BOT | DAY11AMB6E0 | REV:E | MODEL:Y11A | 16.5
User.45: XY-Check rotation:Nov 11 12:15:50 2013 | XY-Check txt overlap:Nov 11 12:15:01 2013 | XY-Check txt:Nov 11 12:22:24 2013 | XY-Norefdes:Nov 11 12:15:43 2013 | check acute:Nov 05 19:06:46 2013 | check cline width:Nov 06 11:34:15 2013 | check rotation:Nov 10 14:01:10 2013 | check txt overlap:Nov 10 14:17:29 2013 | create nettxt:Nov 04 15:37:34 2013 | create plane:Nov 06 12:56:25 2013 | cross plane-BOTTOM-SVCC:Nov 05 19:22:03 2013 | cross plane-IN1-SGND:Nov 05 19:21:27 2013 | cross plane-IN2-SVCC:Nov 05 19:21:45 2013 | cross plane-TOP-SGND:Nov 05 19:20:47 2013 | etch cross-IN1-IN2:Nov 05 19:21:12 2013 | etch ref-BOTTOM-SVCC:Nov 05 19:22:35 2013 | etch ref-IN1-SGND:Nov 05 19:21:44 2013 | etch ref-IN2-SVCC:Nov 05 19:22:03 2013 | etch ref-TOP-SGND:Nov 05 19:21:12 2013 | prop check:Nov 05 19:20:43 2013 | FIGURE | TYPE | Circle | Oblong | SIZE | 10.0 | 12.0 | 14.0 | 22.0 | 24.0 | 28.0 | 35.0 | 39.0 | 91.0 | 102.0 | 118.0 | 126.0 | 142.0 | 146.0 | 148.0 | 354.0 | 31.0 | 40.0 | 43.0 | 47.0 | 55.0 | 63.0 | 98.0 | 197.0 | 59.0x31.0 | 63.0x24.0 | 75.0x31.0 | 91.0x43.0 | 94.0x28.0 | 102.0x31.0 | DRILL CHART: TOP to BOTTOM | ALL UNITS ARE IN MILS | TOLERANCE | +0.0/-0.0 | +3.0/-3.0 | PLATED | NON-PLATED | ROTATION | - | 90.000 | 0.000 | QTY | 3841 | 40 | 449 | 19 | 6 | 25 | 8 | 28 | 2 | 1 | 11 | 3 | 4 | 4464 | 26 | 49 | TOTAL HOLES:
